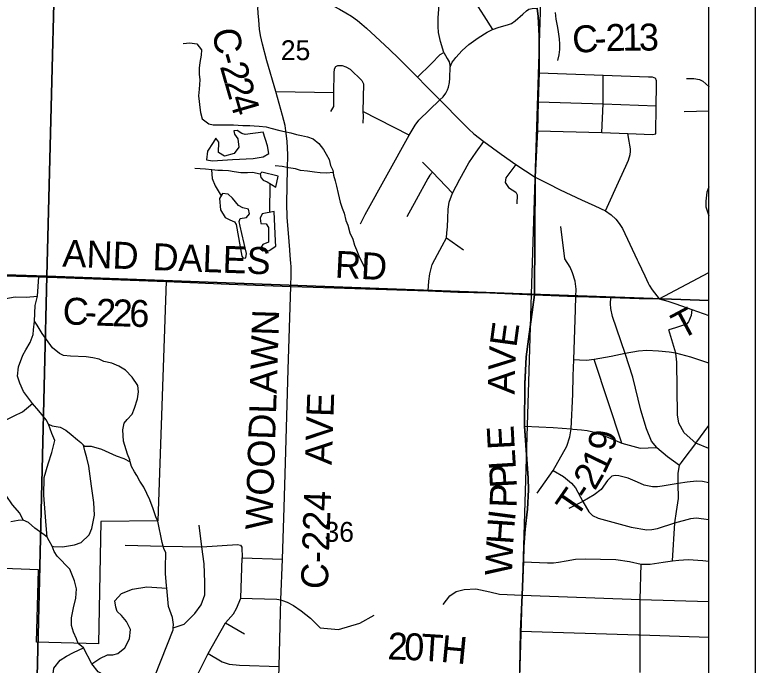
# Model space of a CAD drawing. Extents: x 0 to 34, y 0 to 22.
# Drawn here: x 8.174 to 9.735, y 15.003 to 16.375 of the extents above; entities that cross this region are included whole.
import ezdxf

# ---------------------------------------------------------------- set-up
doc = ezdxf.new("R2010")
doc.units = 0
for name, color, linetype in [('GM_X_City_Street', 7, 'Continuous'), ('GM_X_Corporation', 7, 'Continuous'), ('GM_X_County_Road', 7, 'Continuous'), ('GM_X_County_Road_Text', 7, 'Continuous'), ('GM_X_Minor_Lake', 7, 'Continuous'), ('GM_X_Minor_River', 7, 'Continuous'), ('GM_X_Section_Text', 7, 'Continuous'), ('GM_X_State_Route', 7, 'Continuous'), ('GM_X_Township_Road', 7, 'Continuous'), ('GM_X_Township_Road_Text', 7, 'Continuous'), ('SH_Data', 7, 'Continuous')]:
    doc.layers.add(name, color=color, linetype=linetype)

msp = doc.modelspace()

# ---------------------------------------------------------------- linework, layer by layer
at = {"layer": 'GM_X_City_Street'}
for points in [[(8.3072, 15.0489), (8.3039, 15.0589), (8.2973, 15.0729), (8.293, 15.0868), (8.2929, 15.1028), (8.2973, 15.1242), (8.3019, 15.1446), (8.3039, 15.1642), (8.2993, 15.1808), (8.2894, 15.2055), (8.2626, 15.2333), (8.2566, 15.2427), (8.2523, 15.254), (8.2462, 15.2656), (8.242, 15.2732), (8.2396, 15.2978), (8.2348, 15.3615), (8.2353, 15.3987), (8.2438, 15.4276), (8.2516, 15.452), (8.2577, 15.4768), (8.2518, 15.4915), (8.2445, 15.5114), (8.2399, 15.5209), (8.2244, 15.5395), (8.2112, 15.5553), (8.1916, 15.5801), (8.1845, 15.5979), (8.1794, 15.6129), (8.181, 15.6326), (8.1905, 15.6573), (8.197, 15.668), (8.206, 15.6836), (8.212, 15.7004), (8.2132, 15.7106), (8.2152, 15.7288), (8.2162, 15.7614), (8.2215, 15.7817), (8.2239, 15.8224)], [(8.1543, 15.7763), (8.1742, 15.78), (8.1977, 15.779), (8.2215, 15.7817)], [(8.4752, 15.3067), (8.4713, 15.3161), (8.4652, 15.3327), (8.458, 15.3517), (8.4459, 15.3788), (8.4374, 15.3913), (8.4307, 15.403), (8.4261, 15.4112), (8.4198, 15.4225), (8.417, 15.4322), (8.4159, 15.4364), (8.4111, 15.4484), (8.4031, 15.4753), (8.4016, 15.4997), (8.4044, 15.5137), (8.4104, 15.521), (8.4208, 15.5327), (8.4263, 15.5454), (8.4321, 15.5649), (8.4346, 15.5796), (8.4329, 15.593), (8.4208, 15.6103), (8.407, 15.6253), (8.393, 15.6335), (8.3781, 15.6399), (8.3616, 15.6436), (8.3512, 15.6487), (8.3384, 15.6511), (8.3241, 15.6533), (8.2912, 15.6547), (8.2765, 15.6565), (8.2679, 15.6603), (8.2533, 15.6727), (8.2315, 15.703), (8.2205, 15.7206), (8.2152, 15.7288)], [(8.037, 15.4922), (8.0502, 15.4924), (8.059, 15.4932), (8.0787, 15.5018), (8.0865, 15.5064), (8.0987, 15.5097), (8.1116, 15.5122), (8.1354, 15.5153), (8.1538, 15.5201), (8.1724, 15.5292), (8.1898, 15.5376), (8.2112, 15.5553)], [(8.191, 15.3087), (8.1839, 15.3235), (8.1687, 15.3416), (8.1552, 15.3608), (8.1332, 15.3873), (8.1192, 15.4054), (8.11, 15.421), (8.1042, 15.4342), (8.0984, 15.45), (8.0991, 15.4663), (8.1021, 15.4829), (8.1075, 15.5024), (8.1116, 15.5122)], [(8.2445, 15.5114), (8.2522, 15.5078), (8.2695, 15.5052), (8.281, 15.499), (8.2927, 15.4897), (8.3059, 15.4785), (8.3128, 15.4725), (8.3157, 15.4701), (8.3186, 15.4673), (8.3208, 15.4653), (8.3349, 15.4654), (8.3565, 15.4584), (8.387, 15.4445), (8.4035, 15.4392), (8.417, 15.4322)], [(8.2523, 15.254), (8.2551, 15.2538), (8.2744, 15.2529), (8.2996, 15.2568), (8.3135, 15.2619), (8.3305, 15.2782), (8.336, 15.2913), (8.3418, 15.3192), (8.3403, 15.3462), (8.3353, 15.3806), (8.3296, 15.4231), (8.3258, 15.4407), (8.3211, 15.455), (8.3186, 15.4673)], [(8.242, 15.2732), (8.2354, 15.2782), (8.2155, 15.2924), (8.2024, 15.304), (8.191, 15.3087), (8.1809, 15.3084), (8.1649, 15.3057)]]:
    msp.add_lwpolyline(points, dxfattribs=at)
at = {"layer": 'GM_X_Corporation'}
for points in [[(7.1023, 20.9204), (2.837, 20.9204), (2.837, 14.1204), (9.637, 14.1204), (9.637, 20.9204), (9.4036, 20.9204), (9.4022, 20.8667), (9.2273, 20.8723), (9.1354, 20.8749), (9.124, 20.8753), (8.9858, 20.878), (8.9676, 20.8785), (8.8663, 20.881), (8.6259, 20.8892), (8.5535, 20.8914), (8.5421, 20.8915), (8.4667, 20.8934), (8.0602, 20.9055), (7.9522, 20.9084), (7.1104, 20.9188)], [(7.2756, 16.8704), (8.2669, 16.8377), (8.2409, 15.8234), (7.2356, 15.8559)], [(8.2669, 16.8377), (9.2937, 16.8089), (9.2941, 16.7789), (9.2625, 15.7858), (8.2409, 15.8234)], [(9.637, 15.7721), (9.637, 16.7685), (9.2941, 16.7789), (9.2625, 15.7858)], [(8.2409, 15.8234), (8.2165, 14.8042), (7.2089, 14.8416), (7.2356, 15.8559)], [(8.2307, 15.8231), (8.4926, 15.8129), (8.475, 15.3073), (8.3547, 15.3061), (8.3504, 15.0484), (8.219, 15.0514), (8.2237, 15.2046), (7.9685, 15.2144), (7.9869, 15.8297)], [(8.2409, 15.8234), (9.2625, 15.7858), (9.2313, 14.7696), (8.2165, 14.8042)], [(9.637, 14.7579), (9.637, 15.7721), (9.2625, 15.7858), (9.2313, 14.7696)]]:
    msp.add_lwpolyline(points, close=True, dxfattribs=at)
for points in [[(9.637, 14.7553), (9.637, 20.8621)], [(9.2753, 16.389), (9.277, 16.3719), (9.2795, 16.3309), (9.2791, 16.253), (9.2775, 16.1916), (9.2757, 16.1308), (9.2709, 16.0333), (9.2695, 15.7845), (9.2567, 15.6909), (9.2523, 15.6537), (9.2494, 15.5964), (9.2485, 15.508), (9.2562, 15.3975), (9.2571, 15.3728), (9.2549, 15.3323), (9.2495, 15.29), (9.2468, 15.2526), (9.2461, 15.2217), (9.2433, 15.1511), (9.24, 15.0747), (9.2383, 14.9943)], [(9.2383, 14.9943), (9.24, 15.0747), (9.2433, 15.1511), (9.2461, 15.2217), (9.2468, 15.2526), (9.2495, 15.29), (9.2549, 15.3323), (9.2571, 15.3728), (9.2562, 15.3975), (9.2485, 15.508), (9.2494, 15.5964), (9.2523, 15.6537), (9.2567, 15.6909), (9.2695, 15.7845), (9.2709, 16.0333), (9.2757, 16.1308), (9.2775, 16.1916), (9.2791, 16.253), (9.2795, 16.3309), (9.277, 16.3719), (9.2753, 16.389)]]:
    msp.add_lwpolyline(points, dxfattribs=at)
at = {"layer": 'GM_X_County_Road'}
msp.add_line((8.6258, 15.8069), (8.7557, 15.8016), dxfattribs=at)
for points in [[(8.7557, 15.8512), (8.7546, 15.867), (8.7537, 15.8789), (8.7508, 15.9143), (8.7479, 15.947), (8.7472, 15.9777), (8.7487, 16.0502), (8.7492, 16.0794), (8.748, 16.1083), (8.7461, 16.1243), (8.7434, 16.1411), (8.7383, 16.1623), (8.7241, 16.213), (8.7053, 16.2774), (8.6958, 16.3127), (8.6918, 16.331), (8.6898, 16.3442), (8.688, 16.3634), (8.6865, 16.3782), (8.6864, 16.39), (8.6865, 16.391)], [(9.2711, 16.0327), (9.2759, 16.1303), (9.2777, 16.1911), (9.2793, 16.2525), (9.2797, 16.3303), (9.2772, 16.3713), (9.2755, 16.3885)], [(9.2511, 15.3003), (9.2551, 15.3318), (9.2574, 15.3722), (9.2564, 15.3969), (9.2487, 15.5075), (9.2496, 15.5958), (9.2525, 15.6532), (9.2569, 15.6903), (9.2697, 15.7839), (9.2711, 16.0327)], [(8.7557, 15.8016), (8.7564, 15.8272), (8.7562, 15.8443), (8.7557, 15.8512)], [(7.926, 15.8309), (7.9871, 15.8292), (8.2239, 15.8224), (8.4358, 15.8145)], [(8.4358, 15.8145), (8.4928, 15.8123), (8.6258, 15.8069)], [(8.7223, 14.7411), (8.7235, 14.7857), (8.7267, 14.8676), (8.7284, 14.9133), (8.7314, 15.0006), (8.734, 15.1141), (8.7347, 15.1409), (8.7378, 15.2268), (8.7414, 15.3356), (8.7443, 15.4296), (8.7502, 15.6266), (8.7557, 15.8016)], [(8.7557, 15.8016), (8.8027, 15.8004), (9.045, 15.7925), (9.1076, 15.7901), (9.1755, 15.7886), (9.2697, 15.7839)], [(9.2697, 15.7839), (9.3566, 15.7809), (9.3607, 15.7808)], [(9.3607, 15.7808), (9.4307, 15.7783), (9.4906, 15.7763), (9.5327, 15.776)], [(9.2302, 14.7659), (9.2304, 14.772), (9.2328, 14.8353), (9.235, 14.8983), (9.2385, 14.9938), (9.2409, 15.0741), (9.2435, 15.1505), (9.2463, 15.2212), (9.247, 15.252), (9.2497, 15.2895), (9.2511, 15.3003)]]:
    msp.add_lwpolyline(points, dxfattribs=at)
at = {"layer": 'GM_X_Minor_Lake'}
for points in [[(8.6592, 16.1227), (8.6524, 16.1245), (8.6428, 16.1305), (8.6352, 16.13), (8.6369, 16.1228), (8.6438, 16.113), (8.6459, 16.096), (8.6363, 16.0825), (8.6159, 16.0769), (8.6032, 16.0847), (8.6041, 16.106), (8.5975, 16.1143), (8.5919, 16.1055), (8.5797, 16.0874), (8.578, 16.0688), (8.5902, 16.0667), (8.6114, 16.0685), (8.6326, 16.0699), (8.6762, 16.0721), (8.6971, 16.075), (8.7091, 16.0824), (8.7066, 16.0987), (8.6975, 16.1275)], [(8.6975, 16.1275), (8.6592, 16.1227)], [(8.7287, 16.0344), (8.6945, 16.0431), (8.6911, 16.0392), (8.6927, 16.032), (8.697, 16.0264), (8.7057, 16.0223), (8.7237, 16.0116)], [(8.7237, 16.0116), (8.7287, 16.0344)], [(8.6521, 15.8658), (8.6552, 15.8613), (8.6605, 15.8625), (8.6619, 15.8712), (8.6526, 15.9137), (8.6486, 15.9288), (8.6466, 15.9387), (8.6491, 15.9452), (8.6624, 15.9472), (8.6687, 15.9549), (8.6667, 15.9648), (8.6541, 15.968), (8.6453, 15.9725), (8.6326, 15.9882), (8.6234, 15.9965), (8.6116, 15.9982), (8.6053, 15.9871), (8.6075, 15.9632), (8.6172, 15.9474), (8.6268, 15.9426), (8.6367, 15.9385), (8.6406, 15.9329)], [(8.7202, 15.9598), (8.6949, 15.9553), (8.6909, 15.9457), (8.6925, 15.9344), (8.7035, 15.9338), (8.7089, 15.9259), (8.7086, 15.8951), (8.6965, 15.8904), (8.6913, 15.8812), (8.6963, 15.8767), (8.71, 15.878), (8.7239, 15.8866), (8.7234, 15.8976)], [(8.7234, 15.8976), (8.7202, 15.9598)], [(8.6406, 15.9329), (8.6521, 15.8658)]]:
    msp.add_lwpolyline(points, dxfattribs=at)
at = {"layer": 'GM_X_Minor_River'}
for points in [[(9.3128, 16.3796), (9.3145, 16.3656), (9.3182, 16.3482), (9.3194, 16.3387), (9.3219, 16.3239), (9.3224, 16.3129), (9.3222, 16.3015), (9.3205, 16.2905), (9.318, 16.2783)], [(8.5284, 16.3143), (8.5428, 16.316), (8.5573, 16.3136), (8.5673, 16.3012), (8.5663, 16.2897), (8.5639, 16.2745), (8.5621, 16.2623), (8.5627, 16.2494), (8.5636, 16.238), (8.5634, 16.2278), (8.562, 16.2179), (8.561, 16.2038), (8.5623, 16.192), (8.564, 16.1795), (8.5653, 16.1689), (8.5689, 16.1553), (8.5827, 16.1452), (8.5922, 16.1427), (8.6081, 16.1425), (8.6222, 16.1431), (8.6347, 16.1425), (8.6446, 16.1419), (8.6541, 16.1413), (8.6689, 16.1411), (8.6783, 16.1409), (8.6886, 16.1399), (8.7038, 16.1382), (8.7133, 16.1357), (8.7323, 16.131), (8.7422, 16.1288), (8.7559, 16.1256), (8.7674, 16.1224), (8.7784, 16.1206), (8.791, 16.1174), (8.8031, 16.1134), (8.815, 16.1036), (8.8243, 16.0909), (8.8305, 16.0811), (8.8364, 16.0698), (8.8396, 16.0573), (8.8439, 16.0474), (8.8455, 16.0368), (8.8495, 16.0247), (8.8519, 16.0137), (8.8552, 15.9982), (8.86, 15.9797), (8.8636, 15.9668), (8.8683, 15.9562), (8.8719, 15.9411), (8.8758, 15.9309), (8.8802, 15.915), (8.8861, 15.9014), (8.89, 15.8893), (8.8939, 15.8794), (8.8991, 15.8662), (8.9038, 15.8556), (8.9111, 15.8425), (8.9155, 15.8307)], [(8.8447, 16.0421), (8.8314, 16.0408), (8.8178, 16.0414), (8.8056, 16.0431), (8.7908, 16.0452), (8.776, 16.0465), (8.7657, 16.0498), (8.7505, 16.0522), (8.7376, 16.0547), (8.7224, 16.0564)], [(8.6911, 16.039), (8.6747, 16.0424), (8.6641, 16.0415), (8.6505, 16.0413), (8.6364, 16.0438), (8.6242, 16.0459), (8.6117, 16.0465), (8.6018, 16.0467), (8.5893, 16.0477), (8.576, 16.049), (8.5642, 16.05), (8.5532, 16.051)], [(8.5884, 16.0478), (8.5899, 16.0294), (8.5958, 16.0139), (8.6085, 15.9928)], [(8.7115, 16.0189), (8.7108, 15.9581)]]:
    msp.add_lwpolyline(points, dxfattribs=at)
at = {"layer": 'GM_X_State_Route'}
for points in [[(8.3316, 16.795), (8.3752, 16.7559), (8.4181, 16.7144), (8.4897, 16.6437), (8.5132, 16.6205), (8.5428, 16.5921), (8.5796, 16.5597), (8.6171, 16.5298), (8.6396, 16.5133), (8.6521, 16.5047), (8.6644, 16.4961), (8.6898, 16.4804), (8.7441, 16.4504), (8.7916, 16.4239), (8.8213, 16.4074), (8.8583, 16.3867), (8.8719, 16.3787), (8.8834, 16.3717), (8.896, 16.363), (8.9057, 16.3552), (8.9153, 16.3465), (8.9343, 16.3289), (8.9639, 16.3015)], [(8.9639, 16.3015), (8.9661, 16.2995), (8.9815, 16.2846), (8.9992, 16.2669), (9.0225, 16.2432), (9.0403, 16.2252), (9.0698, 16.1954), (9.1175, 16.147), (9.1312, 16.1333), (9.1418, 16.1237), (9.1627, 16.1077), (9.1995, 16.0808), (9.2299, 16.0593), (9.2711, 16.0327)], [(9.2711, 16.0327), (9.298, 16.0187), (9.3235, 16.006), (9.3688, 15.9848), (9.3969, 15.9721), (9.4193, 15.9615), (9.4314, 15.9531), (9.441, 15.944), (9.4483, 15.9349), (9.4548, 15.9244), (9.4863, 15.8578), (9.4881, 15.8541)], [(9.4881, 15.8541), (9.5019, 15.8243), (9.5093, 15.8087)], [(9.5093, 15.8087), (9.5114, 15.8043), (9.5175, 15.795), (9.5327, 15.776), (9.5509, 15.7707), (9.5652, 15.7662), (9.5795, 15.7612), (9.6014, 15.7533), (9.637, 15.7408)]]:
    msp.add_lwpolyline(points, dxfattribs=at)
at = {"layer": 'GM_X_Township_Road'}
for p, q in [((8.7241, 16.213), (8.8464, 16.2112)), ((9.0049, 16.1208), (8.9074, 16.1708)), ((9.5851, 16.171), (9.637, 16.1724)), ((9.0842, 15.9046), (9.1195, 15.8791)), ((9.5327, 15.776), (9.637, 15.8316)), ((9.4538, 15.4716), (9.3953, 15.6478)), ((8.6179, 15.0922), (8.6581, 15.0691)), ((9.4892, 15.0664), (9.2409, 15.0741)), ((8.3183, 15.0398), (8.3072, 15.0489)), ((8.3359, 15.0057), (8.3183, 15.0398))]:
    msp.add_line(p, q, dxfattribs=at)
for points in [[(9.0225, 16.2432), (9.0516, 16.2717), (9.0707, 16.2909), (9.0782, 16.2954), (9.0712, 16.3185), (9.067, 16.3373), (9.0662, 16.3502), (9.0665, 16.3684), (9.0689, 16.4056), (9.0705, 16.4514), (9.0724, 16.5127), (9.0588, 16.5267)], [(9.0689, 16.4056), (9.099, 16.4055), (9.1274, 16.4044), (9.1421, 16.4026), (9.1498, 16.3923), (9.163, 16.3724), (9.1811, 16.3438)], [(9.0782, 16.2954), (9.0855, 16.283), (9.0899, 16.2753), (9.092, 16.2652), (9.0961, 16.2747), (9.0993, 16.2794), (9.1036, 16.2845), (9.117, 16.2993), (9.124, 16.306), (9.1312, 16.312), (9.1508, 16.3261), (9.1695, 16.338), (9.1811, 16.3438), (9.1951, 16.3484), (9.2128, 16.3539), (9.2207, 16.3568), (9.2286, 16.3622), (9.2448, 16.376), (9.253, 16.3833), (9.2577, 16.3864), (9.2644, 16.3883), (9.2755, 16.3885)], [(8.8402, 16.1708), (8.8461, 16.1816), (8.8464, 16.2112), (8.8474, 16.2514), (8.8481, 16.2606), (8.8504, 16.2655), (8.855, 16.2681), (8.8625, 16.2681), (8.8637, 16.2678)], [(8.8637, 16.2678), (8.8714, 16.2652), (8.8806, 16.2599), (8.9053, 16.2366), (8.9089, 16.2293), (8.9074, 16.1708), (8.908, 16.1619), (8.9077, 16.1464)], [(8.9028, 15.9342), (8.9125, 15.9535), (9.0049, 16.1208), (9.0177, 16.1419), (9.0256, 16.1524), (9.0698, 16.1954), (9.0768, 16.2021), (9.0823, 16.2099), (9.0858, 16.2163), (9.0883, 16.2224), (9.0903, 16.2324), (9.0911, 16.2413), (9.092, 16.2652)], [(9.2793, 16.2525), (9.4145, 16.2474), (9.51, 16.244), (9.518, 16.2437), (9.5246, 16.2414)], [(9.4112, 16.1263), (9.4145, 16.1869), (9.4145, 16.2474)], [(9.5257, 16.1236), (9.5263, 16.1827), (9.5269, 16.2259), (9.5266, 16.2357), (9.5246, 16.2414)], [(9.5903, 16.2403), (9.6058, 16.2405), (9.6174, 16.2383), (9.6243, 16.2346), (9.631, 16.2295), (9.6369, 16.2233), (9.637, 16.223)], [(9.2777, 16.1911), (9.4145, 16.1869), (9.5263, 16.1827)], [(9.2759, 16.1303), (9.4112, 16.1263), (9.4662, 16.1243), (9.5183, 16.1225), (9.5257, 16.1236)], [(9.4193, 15.9615), (9.4503, 16.0293), (9.4624, 16.0559), (9.4675, 16.068), (9.4711, 16.08), (9.472, 16.0865), (9.4718, 16.0921), (9.4705, 16.1002), (9.4689, 16.1081), (9.4662, 16.1243)], [(9.045, 15.7925), (9.0465, 15.8129), (9.0486, 15.8283), (9.0536, 15.8479), (9.0652, 15.8696), (9.075, 15.8874), (9.0842, 15.9046), (9.0848, 15.915), (9.0863, 15.9277), (9.0867, 15.9449), (9.0872, 15.9651), (9.0896, 15.98), (9.0967, 15.999), (9.1118, 16.0283), (9.131, 16.0623), (9.1462, 16.0854), (9.1627, 16.1077)], [(9.0967, 15.999), (9.0545, 16.0429), (9.0333, 16.0642)], [(9.2299, 16.0593), (9.2091, 16.0308), (9.2074, 16.0212), (9.2148, 16.0109), (9.23, 16.001), (9.2333, 15.9952), (9.2321, 15.9764)], [(9.0545, 16.0429), (9.0491, 16.0368), (9.0447, 16.0293), (9.0203, 15.9843), (9.0005, 15.9486)], [(9.637, 16.0123), (9.6331, 16.0007), (9.631, 15.9821), (9.6306, 15.9701), (9.637, 15.9507)], [(9.3558, 15.7536), (9.3566, 15.7809), (9.3575, 15.7964), (9.3552, 15.8131), (9.3499, 15.8306), (9.3447, 15.8423), (9.3335, 15.8599), (9.3253, 15.9282)], [(9.5276, 15.4624), (9.5163, 15.4753), (9.5058, 15.5016), (9.494, 15.5413), (9.4768, 15.6109), (9.4604, 15.6603), (9.4342, 15.7383), (9.4304, 15.7555), (9.43, 15.7654), (9.4307, 15.7783)], [(9.2753, 15.3659), (9.3092, 15.4141), (9.3378, 15.4651), (9.3443, 15.4848), (9.347, 15.5013), (9.3501, 15.5746), (9.3511, 15.6137), (9.3527, 15.647), (9.3558, 15.7536)], [(9.6014, 15.7533), (9.5997, 15.7404), (9.5946, 15.7272), (9.59, 15.7224), (9.5666, 15.7146), (9.5526, 15.7101)], [(9.637, 15.4598), (9.6101, 15.4711), (9.5854, 15.4931), (9.5736, 15.5134), (9.5713, 15.5309), (9.5698, 15.6421), (9.5674, 15.6614), (9.5526, 15.7101)], [(9.637, 15.6398), (9.6183, 15.6466), (9.5993, 15.6527), (9.5674, 15.6614), (9.5532, 15.6631), (9.5312, 15.6657), (9.5065, 15.6668), (9.4886, 15.6653), (9.4604, 15.6603)], [(9.4604, 15.6603), (9.4311, 15.6543), (9.3953, 15.6478), (9.3794, 15.6459), (9.3641, 15.6466), (9.3527, 15.647)], [(9.2487, 15.5075), (9.309, 15.5041), (9.347, 15.5013), (9.3501, 15.501)], [(9.5794, 15.4305), (9.5871, 15.4411), (9.6076, 15.4677), (9.6101, 15.4711), (9.637, 15.509)], [(9.3501, 15.501), (9.3689, 15.4993), (9.3809, 15.4984), (9.3987, 15.4937), (9.4258, 15.4836), (9.4538, 15.4716), (9.4771, 15.4648), (9.4925, 15.4611), (9.5091, 15.4618), (9.5276, 15.4624), (9.5503, 15.4433), (9.5752, 15.4248)], [(9.5609, 15.2229), (9.5653, 15.3032), (9.5688, 15.327), (9.573, 15.3546), (9.5725, 15.3864), (9.5727, 15.4074), (9.5752, 15.4248), (9.5794, 15.4305)], [(9.3092, 15.4141), (9.3306, 15.4013), (9.3478, 15.387), (9.3557, 15.3769), (9.3715, 15.3487), (9.3839, 15.3266), (9.3921, 15.3191), (9.4041, 15.3131), (9.4732, 15.2945), (9.5065, 15.2888), (9.5171, 15.289), (9.5288, 15.2915), (9.5653, 15.3032), (9.5995, 15.3124), (9.6105, 15.3139), (9.6263, 15.3119), (9.637, 15.3104)], [(9.529, 15.3792), (9.5184, 15.3796), (9.501, 15.3829), (9.4866, 15.3893), (9.467, 15.3973), (9.4477, 15.4028), (9.4398, 15.4035), (9.4323, 15.4017), (9.4237, 15.393), (9.4098, 15.3739), (9.3955, 15.3626), (9.3715, 15.3487), (9.3422, 15.3337)], [(9.637, 15.3879), (9.6236, 15.3906), (9.611, 15.3916), (9.5918, 15.3891), (9.5725, 15.3864), (9.539, 15.3804), (9.529, 15.3792)], [(8.4573, 14.9582), (8.4686, 14.9799), (8.5078, 15.0778), (8.5078, 15.0816), (8.5079, 15.0892), (8.5058, 15.104), (8.4977, 15.1272), (8.4941, 15.1656), (8.4936, 15.1709), (8.4912, 15.1956), (8.4914, 15.2157), (8.4924, 15.2335), (8.4921, 15.24), (8.488, 15.2491), (8.4865, 15.2545), (8.4844, 15.2621), (8.4752, 15.3067)], [(8.5078, 15.0816), (8.5309, 15.0897), (8.5531, 15.1123), (8.5665, 15.1307), (8.5743, 15.1515), (8.5746, 15.1781), (8.5731, 15.2168), (8.5683, 15.2529), (8.5622, 15.2985)], [(8.4064, 15.256), (8.4865, 15.2545), (8.5683, 15.2529), (8.6431, 15.2575), (8.6496, 15.2563), (8.6523, 15.2523), (8.6528, 15.2297), (8.7378, 15.2268)], [(8.5066, 14.9071), (8.5438, 14.9496), (8.5519, 14.9684), (8.5815, 15.0279), (8.6179, 15.0922), (8.6348, 15.1118), (8.6409, 15.1228), (8.6499, 15.1448), (8.6528, 15.2297)], [(9.2463, 15.2212), (9.2972, 15.2193), (9.3094, 15.2191), (9.3202, 15.2202), (9.3361, 15.2235), (9.3563, 15.2271), (9.3762, 15.2274), (9.4413, 15.2263), (9.4698, 15.2216), (9.4943, 15.2165), (9.5137, 15.216), (9.541, 15.2201), (9.5609, 15.2229), (9.5741, 15.2243), (9.5936, 15.2257), (9.6243, 15.2238), (9.637, 15.2226)], [(9.4922, 14.9879), (9.4922, 15.0663), (9.4925, 15.1419), (9.4943, 15.2165)], [(8.3359, 15.0057), (8.3532, 15.0171), (8.3688, 15.0249), (8.3802, 15.0248), (8.3908, 15.0281), (8.4057, 15.0397), (8.4153, 15.0586), (8.4178, 15.0787), (8.4093, 15.0951), (8.3984, 15.1077), (8.3894, 15.1162), (8.3865, 15.1257), (8.3848, 15.1386), (8.3985, 15.1544), (8.4217, 15.1633), (8.452, 15.1683), (8.4941, 15.1656)], [(9.0766, 15.1309), (9.0911, 15.1492), (9.104, 15.1589), (9.1213, 15.1627), (9.146, 15.1643), (9.1756, 15.1581), (9.1957, 15.1526), (9.2435, 15.1505)], [(9.2435, 15.1505), (9.4925, 15.1419), (9.637, 15.1372)], [(8.6499, 15.1448), (8.6738, 15.1441), (8.7264, 15.1427), (8.7347, 15.1409), (8.7384, 15.1396)], [(8.7384, 15.1396), (8.7478, 15.1361), (8.7613, 15.129), (8.7776, 15.1178), (8.7972, 15.102), (8.8175, 15.0819), (8.8564, 15.0785), (8.9015, 15.0921), (8.9312, 15.1085)], [(9.637, 15.0616), (9.4922, 15.0663), (9.4892, 15.0664)], [(8.2515, 14.8352), (8.2479, 14.8849), (8.2517, 14.9627), (8.2559, 14.9972), (8.2693, 15.0134), (8.2826, 15.022), (8.297, 15.0302), (8.3183, 15.0398)], [(8.5815, 15.0279), (8.611, 15.01), (8.6253, 15.0053), (8.6473, 15.0035), (8.7314, 15.0006)], [(8.4416, 14.9643), (8.4105, 14.9762), (8.4011, 14.9786), (8.3865, 14.9766), (8.3712, 14.9761), (8.3612, 14.9826), (8.3494, 14.989), (8.3359, 15.0057)]]:
    msp.add_lwpolyline(points, dxfattribs=at)
at = {"layer": 'SH_Data'}
msp.add_line((9.7349, 21.0001), (9.7349, 14.0001), dxfattribs=at)

# ---------------------------------------------------------------- texts
at = {"layer": 'GM_X_County_Road_Text'}
for s, height, rotation, p in [('C', 0.0568, 3.7416, (9.3509, 16.294)), ('2', 0.0568, 1.5406, (9.4202, 16.298)), ('1', 0.0568, 0.6765, (9.455, 16.2989)), ('3', 0.0568, 0.4215, (9.4899, 16.2993)), ('C', 0.0568, 278.7886, (8.5902, 16.3426)), ('-', 0.0568, 2.3814, (9.3971, 16.297)), ('-', 0.0568, 286.1466, (8.599, 16.2887)), ('2', 0.0568, 286.0448, (8.6055, 16.2663)), ('2', 0.0568, 286.2246, (8.6153, 16.2325)), ('4', 0.0568, 286.2575, (8.625, 16.1988)), ('AND', 0.05682, 357.7853, (8.2733, 15.844)), ('DALES', 0.05682, 357.8714, (8.4632, 15.8365)), ('RD', 0.05682, 357.0388, (8.8477, 15.8206)), ('C', 0.0568, 357.8841, (8.2737, 15.7222)), ('2', 0.0568, 357.9213, (8.3437, 15.7196)), ('2', 0.0568, 358.0376, (8.3788, 15.7183)), ('6', 0.0568, 358.6711, (8.4145, 15.7171)), ('-', 0.0568, 357.8763, (8.3204, 15.7204)), ('WOODLAWN', 0.05682, 88.1994, (8.7167, 15.2882)), ('E', 0.0568, 82.3142, (9.2312, 15.6721)), ('V', 0.0568, 86.9167, (9.2286, 15.6233)), ('A', 0.0568, 88.7395, (9.2275, 15.5738)), ('AVE', 0.05682, 87.9903, (8.8419, 15.4248)), ('E', 0.0568, 93.0355, (9.228, 15.4593)), ('L', 0.0568, 93.5481, (9.2306, 15.417)), ('P', 0.0568, 93.1528, (9.2327, 15.3783)), ('P', 0.0568, 87.8971, (9.2314, 15.3344)), ('C-224', 0.05682, 88.0719, (8.8336, 15.163)), ('I', 0.0568, 82.4616, (9.2278, 15.3055)), ('H', 0.0568, 86.048, (9.2245, 15.2566)), ('W', 0.0568, 87.5646, (9.2217, 15.1912))]:
    msp.add_text(s, height=height, rotation=rotation, dxfattribs=at).set_placement(p)
at = {"layer": 'GM_X_Section_Text'}
for s, p in [('25', (8.7345, 16.2792)), ('36', (8.8266, 15.2634))]:
    msp.add_text(s, height=0.04186, rotation=0, dxfattribs=at).set_placement(p)
at = {"layer": 'GM_X_Township_Road_Text'}
for s, rotation, p in [('T', 28.0985, (9.5789, 15.6887)), ('9', 80.5408, (9.4374, 15.4524)), ('1', 64.1609, (9.4168, 15.4041)), ('2', 59.7034, (9.3969, 15.3697)), ('T', 55.3506, (9.3575, 15.3112)), ('-', 56.9908, (9.3827, 15.3476)), ('2', 358.0534, (8.959, 15.0155)), ('0', 357.8242, (8.9939, 15.0143)), ('T', 356.3806, (9.0285, 15.013)), ('H', 354.4946, (9.0704, 15.0104))]:
    msp.add_text(s, height=0.0568, rotation=rotation, dxfattribs=at).set_placement(p)

doc.saveas('drawing.dxf')
